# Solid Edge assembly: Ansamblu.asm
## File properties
Author: Ionut
Template: Normal.asm
Last saved by: Ionut
Revision: 7
Application: Solid Edge
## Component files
baza.par
ax.par
Interference1.par
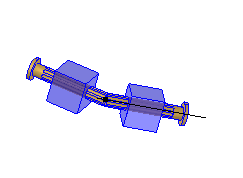
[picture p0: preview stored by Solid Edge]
